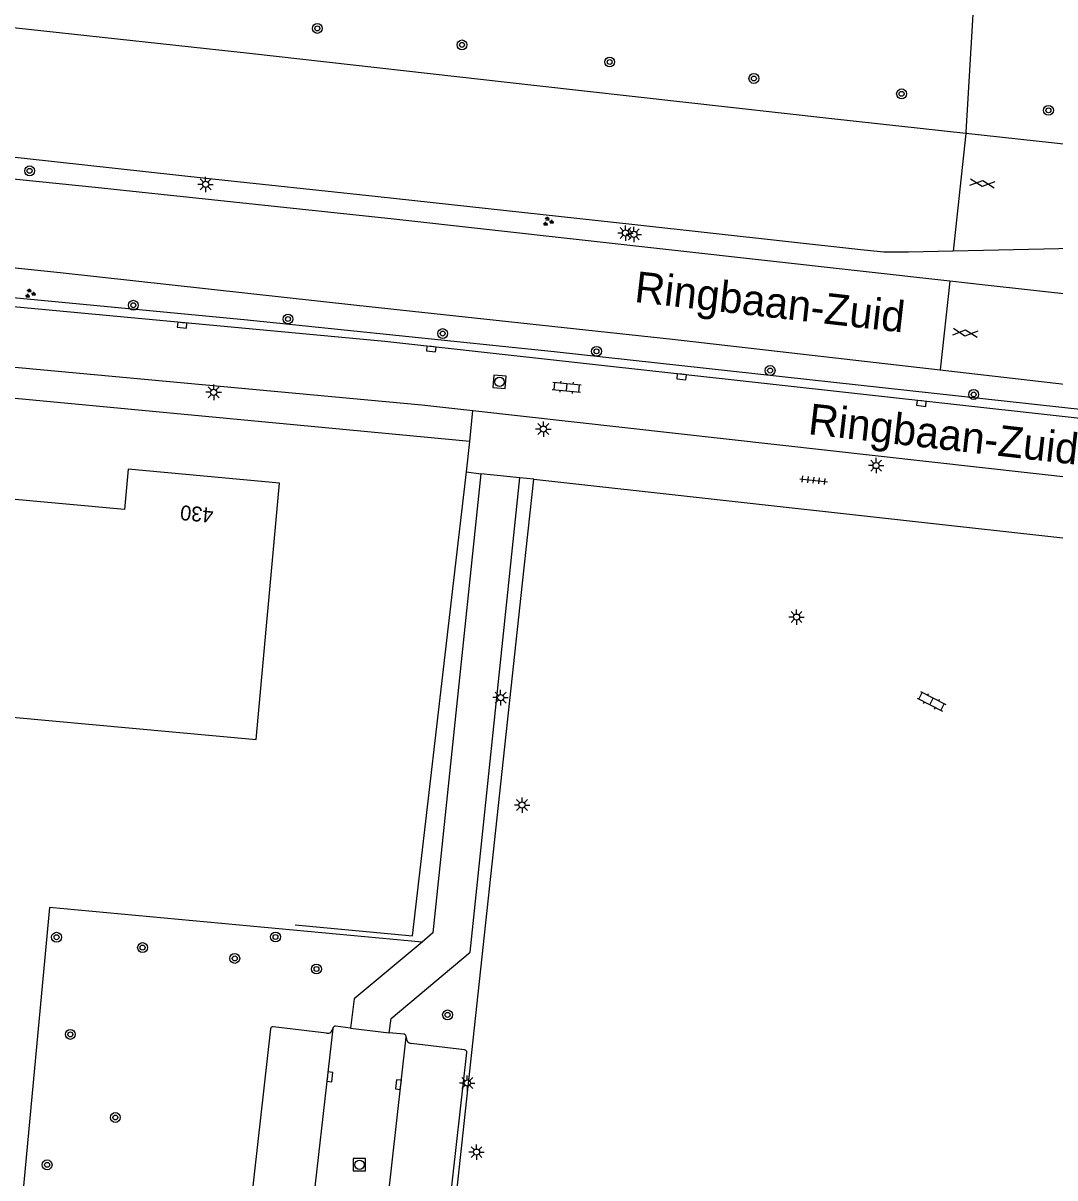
# Model space of a CAD drawing. Extents: x 132994 to 136000, y 393499 to 395512.
# Drawn here: x 133611.6 to 133695.1, y 394951.9 to 395045.3 of the extents above; entities that cross this region are included whole.
import ezdxf

# ---------------------------------------------------------------- set-up
doc = ezdxf.new("R2010")
doc.units = 0
for name, color, linetype in [('gg-afsc-hekwerk', 7, 'Continuous'), ('gg-anno-openbare ruimte label', 7, 'Continuous'), ('gg-knt-verharding', 7, 'Continuous'), ('gg-knt-verharding nz', 7, 'Continuous'), ('gt-anno-plantopografie huisnummer', 7, 'Continuous'), ('gt-bbg-plantopografie pand', 7, 'Continuous'), ('gt-grn-groengrens', 7, 'Continuous'), ('gt-grn-weggrens', 7, 'Continuous'), ('gt-symb-boom', 7, 'Continuous'), ('gt-symb-gesloten verharding', 7, 'Continuous'), ('gt-symb-groenvak', 7, 'Continuous'), ('gt-symb-klinker verharding', 7, 'Continuous'), ('gt-symb-kolk', 7, 'Continuous'), ('gt-symb-lichtmast', 7, 'Continuous'), ('gt-symb-rioolschacht', 7, 'Continuous'), ('gt-symb-tegel verharding', 7, 'Continuous')]:
    doc.layers.add(name, color=color, linetype=linetype)

# ---------------------------------------------------------------- blocks, each defined once
blk = doc.blocks.new('gt0-BOOM')
at = {"layer": 'gt-symb-boom'}
for radius in [0.4, 0.2]:
    blk.add_circle((0, 0), radius, dxfattribs=at)
blk = doc.blocks.new('gt0-LMAST')
at = {"layer": 'gt-symb-lichtmast'}
for p, q in [((-0.182, 0.173), (-0.447, 0.438)), ((-0.005, 0.246), (-0.005, 0.621)), ((0.172, 0.173), (0.437, 0.438)), ((-0.255, -0.004), (-0.63, -0.004)), ((-0.182, -0.181), (-0.447, -0.446)), ((-0.005, -0.254), (-0.005, -0.629)), ((0.437, -0.446), (0.172, -0.181)), ((0.245, -0.004), (0.62, -0.004))]:
    blk.add_line(p, q, dxfattribs=at)
blk.add_circle((-0.005, -0.004), 0.25, dxfattribs=at)
blk = doc.blocks.new('gt0-KL1')
at = {"layer": 'gt-symb-klinker verharding'}
for p, q in [((-1.15, 0.3), (1.15, 0.3)), ((-1, -0.3), (-1, 0.3)), ((-0.5, 0.3), (-0.5, 0.45)), ((0, -0.3), (0, 0.3)), ((0.5, 0.3), (0.5, 0.45)), ((1, -0.3), (1, 0.3)), ((-1.15, -0.3), (1.15, -0.3)), ((-0.5, -0.45), (-0.5, -0.3)), ((0.5, -0.45), (0.5, -0.3))]:
    blk.add_line(p, q, dxfattribs=at)
blk = doc.blocks.new('gt0-KOLK')
at = {"layer": 'gt-symb-kolk'}
blk.add_lwpolyline([(0, 0), (0.375, 0), (0.375, 0.4), (-0.375, 0.4), (-0.375, 0), (0, 0)], dxfattribs=at)
blk = doc.blocks.new('gt0-RS')
at = {"layer": 'gt-symb-rioolschacht'}
blk.add_lwpolyline([(-0.5, -0.5), (0.5, -0.5), (0.5, 0.5), (-0.5, 0.5)], close=True, dxfattribs=at)
blk.add_circle((0, 0), 0.375, dxfattribs=at)
blk = doc.blocks.new('gt0-TEG1')
at = {"layer": 'gt-symb-tegel verharding'}
for p, q in [((-1.125, 0), (1.125, 0)), ((-0.9, -0.25), (-0.9, 0.25)), ((-0.45, -0.25), (-0.45, 0.25)), ((0, -0.25), (0, 0.25)), ((0.45, -0.25), (0.45, 0.25)), ((0.9, -0.25), (0.9, 0.25))]:
    blk.add_line(p, q, dxfattribs=at)
blk = doc.blocks.new('gt0-GRVAK')
at = {"layer": 'gt-symb-groenvak'}
for p, q in [((-0.11, 0.189), (-0.228, 0.24)), ((-0.182, 0.153), (0.088, 0.153)), ((-0.091, 0.211), (-0.156, 0.322)), ((-0.047, 0.214), (-0.047, 0.393)), ((-0.004, 0.211), (0.061, 0.322)), ((0.015, 0.189), (0.133, 0.24)), ((0.262, -0.052), (0.197, 0.059)), ((0.305, -0.049), (0.305, 0.13)), ((0.349, -0.052), (0.414, 0.059)), ((-0.245, -0.228), (-0.363, -0.177)), ((-0.318, -0.264), (-0.047, -0.264)), ((-0.226, -0.206), (-0.291, -0.095)), ((-0.183, -0.203), (-0.183, -0.024)), ((-0.139, -0.206), (-0.074, -0.095)), ((-0.12, -0.228), (-0.002, -0.177)), ((0.243, -0.074), (0.125, -0.023)), ((0.17, -0.11), (0.441, -0.11)), ((0.368, -0.074), (0.486, -0.023))]:
    blk.add_line(p, q, dxfattribs=at)
blk = doc.blocks.new('gt0-GESVH1')
at = {"layer": 'gt-symb-gesloten verharding'}
for p, q in [((-0.992, -0.261), (0.008, 0.239)), ((0.008, -0.261), (-0.992, 0.239)), ((0.008, 0.239), (1.008, -0.261)), ((1.008, 0.239), (0.008, -0.261))]:
    blk.add_line(p, q, dxfattribs=at)

msp = doc.modelspace()

# ---------------------------------------------------------------- linework, layer by layer
at = {"layer": 'gg-afsc-hekwerk'}
for p, q in [((133647.501, 395009.006), (133647.787, 395011.465)), ((133646.453, 395000), (133647.501, 395009.006)), ((133647.501, 395009.006), (133648.658, 395008.86)), ((133651.823, 395008.531), (133648.658, 395008.86)), ((133652.953, 395008.413), (133651.823, 395008.531)), ((133652.045, 395000), (133652.953, 395008.413)), ((133652.953, 395008.413), (133701.674, 395003.029)), ((133643.133, 394971.465), (133646.453, 395000)), ((133645.689, 394941.07), (133652.045, 395000)), ((133633.647, 394972.356), (133643.133, 394971.465))]:
    msp.add_line(p, q, dxfattribs=at)
at = {"layer": 'gg-knt-verharding'}
for p, q in [((133647.787, 395011.465), (133572.806, 395018.557)), ((133648.024, 395013.974), (133732.946, 395004.495)), ((133631.645, 394963.952), (133629.407, 394944.048)), ((133636.178, 394963.59), (133631.866, 394964.11)), ((133638.126, 394963.999), (133636.916, 394964.147)), ((133638.126, 394963.999), (133641.254, 394963.612)), ((133642.473, 394963.499), (133641.254, 394963.612)), ((133647.361, 394962.245), (133643.034, 394962.764)), ((133645.302, 394942.105), (133647.534, 394962.031))]:
    msp.add_line(p, q, dxfattribs=at)
for points in [[(133687.93, 395036.393), (133677.074, 395037.572), (133652.947, 395040.265), (133629.956, 395042.856), (133606.08, 395045.44), (133558.796, 395050.727), (133544.361, 395052.473)], [(133686.896, 395026.871), (133683.271, 395026.792), (133681.29, 395026.778), (133679.415, 395026.964), (133661.135, 395029.005), (133640.108, 395031.29), (133626.428, 395032.741), (133607.027, 395034.888), (133591.631, 395036.509), (133569.178, 395038.989), (133550.591, 395041.067), (133542.858, 395041.974)], [(133686.631, 395024.429), (133641.633, 395029.446), (133617.457, 395032.005), (133593.838, 395034.41), (133570.777, 395036.812), (133548.277, 395039.242), (133542.645, 395039.797)], [(133746.282, 395030.078), (133723.561, 395032.515), (133687.93, 395036.393)], [(133566.956, 395030.081), (133588.709, 395027.838), (133614.632, 395025.129), (133638.623, 395022.498), (133664.178, 395019.754), (133685.853, 395017.266)], [(133874.225, 395008.567), (133868.836, 395009.122), (133845.49, 395011.838), (133822.318, 395014.495), (133750.599, 395022.315), (133724.94, 395025.159), (133706.97, 395027.168), (133704.01, 395027.246), (133686.896, 395026.871)], [(133733.476, 395009.301), (133640.903, 395019.557), (133605.015, 395022.912), (133570.729, 395026.044)], [(133781.477, 395014.524), (133761.294, 395016.152), (133739.879, 395018.515), (133712.712, 395021.56), (133689.496, 395024.11), (133686.631, 395024.429)], [(133573.042, 395020.974), (133643.908, 395014.433), (133648.024, 395013.974)], [(133685.853, 395017.266), (133710.428, 395014.444), (133733.641, 395011.92), (133754.939, 395009.49), (133767.315, 395008.188)], [(133641.254, 394963.612), (133641.405, 394964.767), (133647.809, 394970.138), (133651.823, 395008.531)], [(133648.658, 395008.86), (133644.791, 394971.699), (133643.913, 394970.966)], [(133643.913, 394970.966), (133638.405, 394966.368), (133638.126, 394963.999)]]:
    msp.add_lwpolyline(points, dxfattribs=at)
for centre, radius, start, end in [((133631.837, 394963.917), 0.195, 81.4263, 169.69809), ((133636.253, 394964.031), 0.447, 260.39392, 352.56321), ((133636.878, 394963.969), 0.182, 77.89726, 178.78432), ((133642.419, 394963.289), 0.217, 351.23442, 75.49029), ((133643.082, 394963.213), 0.452, 174.52495, 263.83792), ((133647.337, 394962.049), 0.198, 354.88303, 83.02189)]:
    msp.add_arc(centre, radius, start, end, dxfattribs=at)
at = {"layer": 'gg-knt-verharding nz'}
msp.add_line((133640.244, 394942.084), (133642.633, 394963.256), dxfattribs=at)
msp.add_lwpolyline([(133636.696, 394963.973), (133634.725, 394946.644), (133634.31, 394942.801)], dxfattribs=at)
at = {"layer": 'gt-bbg-plantopografie pand'}
msp.add_lwpolyline([(133536.743, 394971.426), (133531.768, 394916.893), (133577.105, 394913.177), (133584.257, 394991.579), (133630.474, 394987.363), (133632.366, 395008.1), (133620.139, 395009.215), (133619.843, 395005.97), (133569.623, 395010.551), (133569.85, 395013.05), (133528.588, 395016.814), (133528.024, 395010.625)], dxfattribs=at)
at = {"layer": 'gt-grn-groengrens'}
for q in [(133688.756, 395049.85), (133687.93, 395036.393)]:
    msp.add_line((133687.942, 395036.505), q, dxfattribs=at)
for points in [[(133568.55, 395027.016), (133598.605, 395024.265), (133629.508, 395021.349), (133654.602, 395018.736), (133699.62, 395013.815), (133719.54, 395011.607), (133729.257, 395010.661), (133736.756, 395009.518), (133740.544, 395009.001), (133753.397, 395006.823), (133760.835, 395005.738), (133823.139, 394998.553), (133826.998, 394998.206), (133842.575, 394996.032), (133846.453, 394995.188)], [(133643.913, 394970.966), (133613.761, 394973.747), (133607.969, 394911.905)]]:
    msp.add_lwpolyline(points, dxfattribs=at)
at = {"layer": 'gt-grn-weggrens'}
for p, q in [((133687.93, 395036.393), (133686.896, 395026.871)), ((133686.631, 395024.429), (133685.853, 395017.266)), ((133647.787, 395011.465), (133648.024, 395013.974))]:
    msp.add_line(p, q, dxfattribs=at)

# ---------------------------------------------------------------- block references
at = {"layer": 'gt-symb-boom'}
for p in [(133635.438, 395044.891), (133647.143, 395043.556), (133659.098, 395042.173), (133670.769, 395040.838), (133682.722, 395039.595), (133694.608, 395038.262), (133612.152, 395033.365), (133620.549, 395022.492), (133633.065, 395021.376), (133645.579, 395020.198), (133658.032, 395018.764), (133672.079, 395017.206), (133688.555, 395015.271), (133614.331, 394971.352), (133632.054, 394971.372), (133621.293, 394970.513), (133628.752, 394969.638), (133635.368, 394968.78), (133645.979, 394965.068), (133615.449, 394963.49), (133619.087, 394956.766), (133613.567, 394952.936)]:
    msp.add_blockref('gt0-BOOM', p, dxfattribs=at)
at = {"layer": 'gt-symb-gesloten verharding'}
for p, rotation in [((133689.252, 395032.35), -6.14399576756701), ((133687.871, 395020.262), -6.14399576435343)]:
    msp.add_blockref('gt0-GESVH1', p, dxfattribs=dict(at, rotation=rotation))
at = {"layer": 'gt-symb-groenvak'}
for p in [(133654.099, 395029.259), (133612.18, 395023.437)]:
    msp.add_blockref('gt0-GRVAK', p, dxfattribs=at)
at = {"layer": 'gt-symb-klinker verharding'}
for p, rotation in [((133655.622, 395015.855), -5.51097695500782), ((133685.15, 394990.435), -27.256871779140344)]:
    msp.add_blockref('gt0-KL1', p, dxfattribs=dict(at, rotation=rotation))
at = {"layer": 'gt-symb-kolk'}
for p, rotation in [((133624.51, 395021.076), 174.60853660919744), ((133644.683, 395019.146), 173.79902900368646), ((133664.937, 395016.904), 173.6851155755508), ((133684.349, 395014.749), 173.6851155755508), ((133636.254, 394960.083), -96.48544256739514), ((133642.194, 394959.407), 83.48959062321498)]:
    msp.add_blockref('gt0-KOLK', p, dxfattribs=dict(at, rotation=rotation))
at = {"layer": 'gt-symb-lichtmast'}
for p in [(133626.4, 395032.273), (133660.383, 395028.333), (133661.058, 395028.227), (133627.057, 395015.452), (133653.734, 395012.473), (133680.667, 395009.522), (133674.223, 394997.258), (133650.274, 394990.744), (133652.011, 394982.051), (133647.575, 394959.556), (133648.326, 394953.968)]:
    msp.add_blockref('gt0-LMAST', p, dxfattribs=at)
at = {"layer": 'gt-symb-rioolschacht', "rotation": -94.82076607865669}
msp.add_blockref('gt0-RS', (133650.188, 395016.29), dxfattribs=at)
at = {"layer": 'gt-symb-rioolschacht'}
msp.add_blockref('gt0-RS', (133638.848, 394952.94), dxfattribs=at)
at = {"layer": 'gt-symb-tegel verharding', "rotation": -6.485660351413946}
msp.add_blockref('gt0-TEG1', (133675.606, 395008.33), dxfattribs=at)

# ---------------------------------------------------------------- texts
at = {"layer": 'gg-anno-openbare ruimte label'}
for p in [(133661.036, 395022.766), (133675.092, 395012.069)]:
    msp.add_text('Ringbaan-Zuid', height=2.5, rotation=353.5, dxfattribs=at).set_placement(p)
at = {"layer": 'gt-anno-plantopografie huisnummer'}
msp.add_text('430', height=1.2, rotation=174.78804, dxfattribs=at).set_placement((133627.07, 395006.073))

doc.saveas('drawing.dxf')
